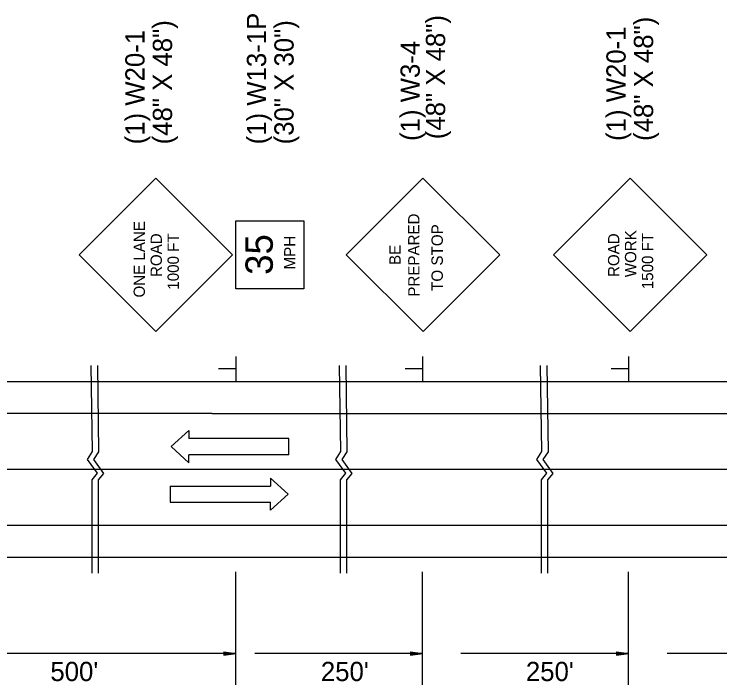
# Model space of a CAD drawing. Extents: x 1678017 to 1687792, y 404433 to 413488.
# Drawn here: x 1680575.7 to 1680795.5, y 404723.6 to 404932.6 of the extents above; entities that cross this region are included whole.
import ezdxf

# ---------------------------------------------------------------- set-up
doc = ezdxf.new("R2010")
doc.units = 0
doc.layers.add('Default', color=7, linetype='Continuous')
doc.layers.add('S_GRAVEL_ROAD', color=7, linetype='Continuous')

msp = doc.modelspace()

# ---------------------------------------------------------------- linework, layer by layer
at = {"layer": 'Default'}
for p, q in [((1680619.8, 404881.52), (1680595.9, 404857.62)), ((1680619.8, 404881.52), (1680643.68, 404857.62)), ((1680702.96, 404881.52), (1680679.12, 404857.58)), ((1680702.96, 404881.52), (1680726.91, 404857.66)), ((1680767.53, 404881.52), (1680743.63, 404857.62)), ((1680767.53, 404881.52), (1680791.42, 404857.62)), ((1680595.9, 404857.62), (1680619.8, 404833.72)), ((1680643.68, 404857.62), (1680619.8, 404833.72)), ((1680679.12, 404857.58), (1680703.05, 404833.72)), ((1680726.91, 404857.66), (1680703.05, 404833.72)), ((1680743.63, 404857.62), (1680767.53, 404833.72)), ((1680791.42, 404857.62), (1680767.53, 404833.72)), ((1680644.76, 404825.98), (1680644.76, 404818.15)), ((1680702.86, 404825.98), (1680702.86, 404818.15)), ((1680767.02, 404825.98), (1680767.02, 404818.15)), ((1680644.65, 404822.09), (1680639.3, 404822.09)), ((1680702.75, 404822.09), (1680697.41, 404822.09)), ((1680766.91, 404822.09), (1680761.57, 404822.09)), ((1680081.8, 404818.15), (1680990.32, 404818.15)), ((1680637.3, 404808.15), (1680514.26, 404808.15)), ((1680637.3, 404808.15), (1680990.32, 404808.15)), ((1680990.32, 404790.77), (1680548.11, 404790.77)), ((1680519.97, 404773.39), (1680637.3, 404773.39)), ((1680637.3, 404773.39), (1680990.32, 404773.39)), ((1680081.8, 404763.39), (1680990.32, 404763.39)), ((1680644.76, 404723.6), (1680644.76, 404758.81)), ((1680702.86, 404723.6), (1680702.86, 404758.81)), ((1680767.02, 404723.6), (1680767.02, 404758.81)), ((1680644.76, 404733.39), (1680554.02, 404733.39)), ((1680641.01, 404733.95), (1680644.76, 404733.39)), ((1680641.01, 404733.95), (1680641.01, 404732.83)), ((1680641.01, 404733.86), (1680644.13, 404733.39)), ((1680641.01, 404733.76), (1680643.49, 404733.39)), ((1680641.01, 404733.67), (1680642.86, 404733.39)), ((1680641.01, 404733.57), (1680642.23, 404733.39)), ((1680641.01, 404733.48), (1680641.6, 404733.39)), ((1680641.01, 404732.83), (1680644.76, 404733.39)), ((1680641.01, 404733.2), (1680642.23, 404733.39)), ((1680641.01, 404733.01), (1680643.49, 404733.39)), ((1680641.01, 404732.92), (1680644.13, 404733.39)), ((1680641.01, 404733.11), (1680642.86, 404733.39)), ((1680641.01, 404733.3), (1680641.6, 404733.39)), ((1680702.86, 404733.39), (1680650.67, 404733.39)), ((1680699.11, 404733.95), (1680702.86, 404733.39)), ((1680699.11, 404733.95), (1680699.11, 404732.83)), ((1680699.11, 404733.86), (1680702.24, 404733.39)), ((1680699.11, 404733.76), (1680701.59, 404733.39)), ((1680699.11, 404733.67), (1680700.97, 404733.39)), ((1680699.11, 404733.57), (1680700.33, 404733.39)), ((1680699.11, 404733.48), (1680699.7, 404733.39)), ((1680699.11, 404732.83), (1680702.86, 404733.39)), ((1680699.11, 404733.2), (1680700.33, 404733.39)), ((1680699.11, 404733.01), (1680701.59, 404733.39)), ((1680699.11, 404732.92), (1680702.24, 404733.39)), ((1680699.11, 404733.11), (1680700.97, 404733.39)), ((1680699.11, 404733.3), (1680699.7, 404733.39)), ((1680767.02, 404733.39), (1680714.83, 404733.39)), ((1680763.27, 404733.95), (1680767.02, 404733.39)), ((1680763.27, 404733.95), (1680763.27, 404732.83)), ((1680763.27, 404733.86), (1680766.4, 404733.39)), ((1680763.27, 404733.76), (1680765.75, 404733.39)), ((1680763.27, 404733.67), (1680765.13, 404733.39)), ((1680763.27, 404733.57), (1680764.49, 404733.39)), ((1680763.27, 404733.48), (1680763.87, 404733.39)), ((1680763.27, 404732.83), (1680767.02, 404733.39)), ((1680763.27, 404733.2), (1680764.49, 404733.39)), ((1680763.27, 404733.01), (1680765.75, 404733.39)), ((1680763.27, 404732.92), (1680766.4, 404733.39)), ((1680763.27, 404733.11), (1680765.13, 404733.39)), ((1680763.27, 404733.3), (1680763.87, 404733.39)), ((1680831.18, 404733.39), (1680778.99, 404733.39))]:
    msp.add_line(p, q, dxfattribs=at)
msp.add_lwpolyline([(1680644.75, 404847.05), (1680644.75, 404868.18), (1680665.88, 404868.18), (1680665.88, 404847.05)], close=True, dxfattribs=at)
for points in [[(1680599.58, 404823.16), (1680599.99, 404796.28), (1680598.36, 404793.87), (1680601.53, 404789.54), (1680599.86, 404787.54), (1680599.86, 404758.39)], [(1680601.58, 404823.16), (1680601.99, 404796.2), (1680600.36, 404793.79), (1680603.53, 404789.46), (1680601.86, 404787.46), (1680601.86, 404758.39)], [(1680676.93, 404823.16), (1680677.34, 404796.28), (1680675.71, 404793.87), (1680678.88, 404789.54), (1680677.21, 404787.54), (1680677.2, 404758.39)], [(1680678.92, 404823.16), (1680679.33, 404796.2), (1680677.71, 404793.79), (1680680.87, 404789.46), (1680679.21, 404787.46), (1680679.2, 404758.39)], [(1680739.52, 404823.16), (1680739.93, 404796.28), (1680738.31, 404793.87), (1680741.47, 404789.54), (1680739.81, 404787.54), (1680739.8, 404758.39)], [(1680741.52, 404823.16), (1680741.93, 404796.2), (1680740.31, 404793.79), (1680743.47, 404789.46), (1680741.81, 404787.46), (1680741.8, 404758.39)]]:
    msp.add_lwpolyline(points, dxfattribs=at)
at = {"layer": 'S_GRAVEL_ROAD'}
for p, q in [((1680624.56, 404797.84), (1680630.04, 404802.84)), ((1680630.04, 404802.84), (1680630.04, 404800.34)), ((1680661.26, 404800.34), (1680630.04, 404800.34)), ((1680661.26, 404795.34), (1680661.26, 404800.34)), ((1680630.04, 404792.84), (1680624.56, 404797.84)), ((1680661.26, 404795.34), (1680630.04, 404795.34)), ((1680630.04, 404792.84), (1680630.04, 404795.34)), ((1680655.52, 404788), (1680661, 404783)), ((1680655.52, 404788), (1680655.52, 404785.5)), ((1680624.3, 404785.5), (1680655.52, 404785.5)), ((1680624.3, 404785.5), (1680624.3, 404780.5)), ((1680661, 404783), (1680655.52, 404778)), ((1680624.3, 404780.5), (1680655.52, 404780.5)), ((1680655.52, 404778), (1680655.52, 404780.5))]:
    msp.add_line(p, q, dxfattribs=at)

# ---------------------------------------------------------------- texts
at = {"layer": 'Default'}
for s, height, rotation, p in [('(1) W13-1P', 6, 90, (1680654.15, 404892.04)), ('(48" X 48")', 6, 90, (1680624.85, 404892.04)), ('(30" X 30")', 6, 90, (1680662.71, 404892.04)), ('(48" X 48")', 6, 90, (1680709.9, 404893.64)), ('(48" X 48")', 6, 90, (1680774.67, 404893.11)), ('(1) W20-1', 6, 90, (1680766.11, 404893.11)), ('(1) W20-1', 6, 90, (1680616.28, 404892.04)), ('(1) W3-4', 6, 90, (1680702, 404893.11)), ('PREPARED', 3.521, 90.1003, (1680701.92, 404844.58)), ('ONE LANE', 3.521, 90.0004, (1680616.39, 404844.32)), ('TO STOP', 3.544, 90.0006, (1680709.18, 404846.36)), ('ROAD', 3.52, 90, (1680621.68, 404850.71)), ('1000 FT', 3.522, 90.0006, (1680626.96, 404846.76)), ('ROAD', 3.521, 90.0004, (1680764.13, 404850.71)), ('WORK', 3.52, 90, (1680769.41, 404850.64)), ('1500 FT', 3.522, 90.0006, (1680774.69, 404846.9)), ('35', 8.51, 90, (1680656.22, 404851.39)), ('MPH', 3.522, 90.0006, (1680663.27, 404853.07)), ('BE', 3.521, 90.1004, (1680696.04, 404854.46))]:
    msp.add_text(s, height=height, rotation=rotation, dxfattribs=at).set_placement(p)
for s, p in [("500'", (1680586.95, 404724.78)), ("250'", (1680671.19, 404724.78)), ("250'", (1680735.04, 404724.78))]:
    msp.add_text(s, height=6, dxfattribs=at).set_placement(p)

doc.saveas('drawing.dxf')
